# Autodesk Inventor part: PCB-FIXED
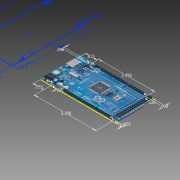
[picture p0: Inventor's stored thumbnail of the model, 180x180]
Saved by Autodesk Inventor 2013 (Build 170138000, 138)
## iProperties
Created: 2012-07
Part Number: PCB-FIXED
Material: Generic
Document SubType Name: Modeling
Designer: Paul
Density: 1 g/cm^3
Author: Paul
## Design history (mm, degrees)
sketch "Sketch1"
  geometry: L1 (-50.8, -26.607)-(50.8, -26.607); L2 (50.8, -26.607)-(50.8, 26.607); L3 (50.8, 26.607)-(-50.8, 26.607); L4 (-50.8, 26.607)-(-50.8, -26.607); L5 (-50.8, -26.607)-(50.8, 26.607); L6 (50.8, -26.607)-(-50.8, 26.607); 1 further point
  constraints: 12 end point, 2 midpoint, 2 parallel, 1 horizontal, 1 perpendicular
  dimensions: "d0" = 101.6 distance of L3.end L2.end; "d1" = 53.213 distance of L2.end L1.end
extrude "Extrusion1" new body sketch "Sketch1" distance "d2" = 1.651; taper "d3" = 0 deg
sketch "Sketch3"
  geometry: L1 (50.8, 26.607)-(-50.8, 26.607) reference; L2 (-50.8, 26.607)-(-50.8, -26.607) reference; C1 r 1.588 at (-36.83, 24.067); C2 r 1.587 at (45.72, 24.067); C3 r 1.588 at (-35.56, -24.193); C4 r 1.588 at (39.37, -24.193); 1 further point
  constraints: 4 centre point
  dimensions: "d4" = 3.175 diameter of C1; "d5" = 2.54 distance from line of L1 C1.centre; "d6" = 13.97 distance from line of L2 C1.centre; "d7" = 3.175 diameter of C2; "d10" = 3.175 diameter of C3; "d12" = 3.175 diameter of C4; "d35" = 50.8 distance from line of L1 C3.centre; "d36" = 15.24 distance from line of L2 C3.centre; "d37" = 2.54 distance from line of L1 C2.centre; "d38" = 96.52 distance from line of L2 C2.centre; "d39" = 50.8 distance from line of L1 C4.centre; "d40" = 90.17 distance from line of L2 C4.centre
extrude "Extrusion2" cut sketch "Sketch3" distance "d16" = 1.651; taper "d17" = 0 deg
chamfer "Chamfer1" distance "d18" = 3.175; stored, may be unused: second distance "d19" = 3.175, angle "d20" = 45 deg
sketch "Sketch5"
  geometry: L1 (-50.8, 26.607)-(50.686, 26.824); L2 (50.686, 26.824)-(50.8, -26.607); L3 (50.8, -26.607)-(-50.686, -26.824); L4 (-50.686, -26.824)-(-50.8, 26.607); 1 further point; 1 other entity
  constraints: 2 other
feature "Decal1" sketch "Sketch5"
sketch "Sketch6"
  geometry: L1 (47.625, 26.607)-(50.8, 23.432) reference; L2 (-50.8, -26.607)-(50.8, -26.607) reference; L3 (50.8, -26.607)-(50.8, 23.432) reference; L4 (50.8, -11.632)-(48.555, -13.877); L5 (48.555, -13.877)-(48.555, -26.607); 1 further point
  constraints: 4 end point, 2 perpendicular, 2 point on line
extrude "Extrusion3" cut sketch "Sketch6" distance "d25" = 1.651; taper "d26" = 0 deg
chamfer "Chamfer2" distance "d27" = 2.286; stored, may be unused: second distance "d28" = 3.175, angle "d29" = 45 deg
sketch "Sketch7"
  geometry: L1 (-50.8, 26.607)-(50.759, 26.684); L2 (50.759, 26.684)-(50.8, -27.082); L3 (50.8, -27.082)-(-50.759, -27.16); L4 (-50.759, -27.16)-(-50.8, 26.607); 1 further point; 1 other entity
  constraints: 2 other
feature "Decal2" sketch "Sketch7"
body "Solid1"
node "Image1"
node "Image2"
